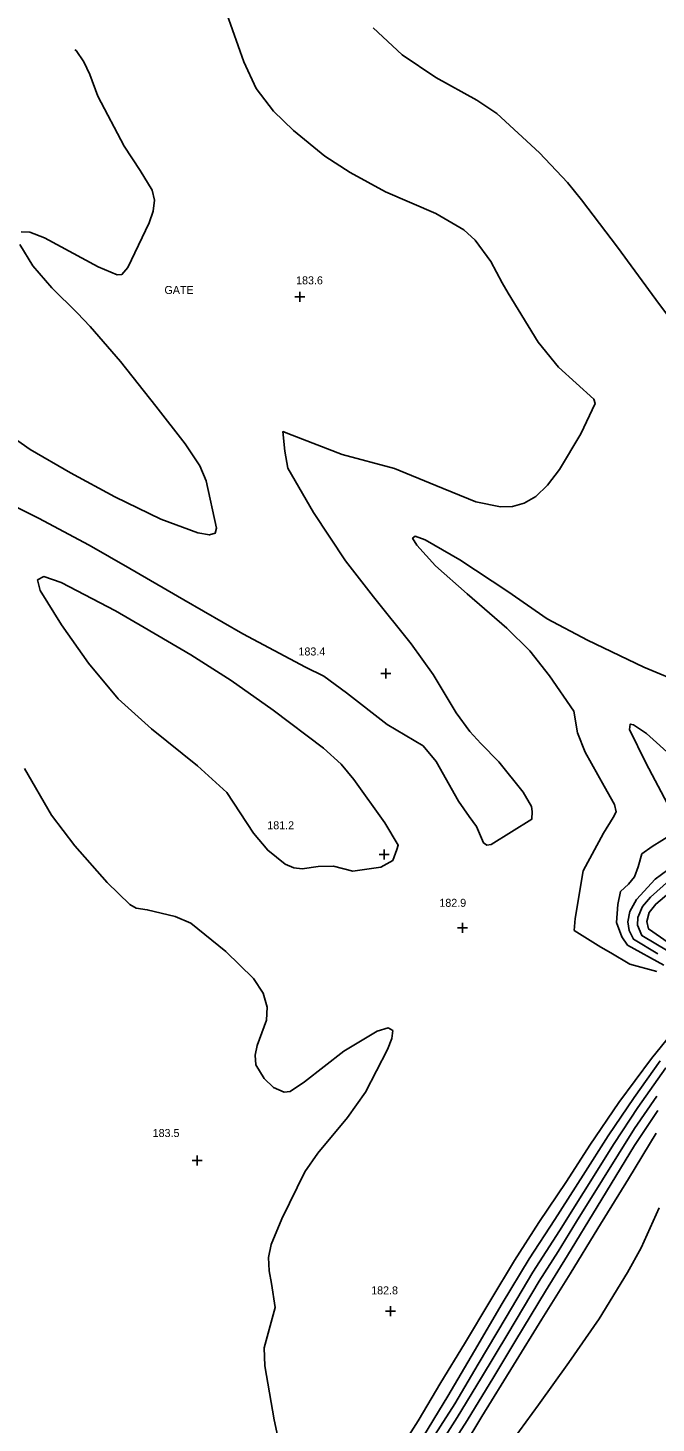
# Model space of a CAD drawing. Extents: x 1467615 to 2003689, y 770235 to 1108726.
# Drawn here: x 1995982 to 1996139.1, y 777168.5 to 777517.3 of the extents above; entities that cross this region are included whole.
import ezdxf

# ---------------------------------------------------------------- set-up
doc = ezdxf.new("R2010")
doc.units = 0
for name, color, linetype in [('RD_DTM_Major1', 7, 'Continuous'), ('RD_DTM_Minor1', 7, 'Continuous'), ('RD_DTM_Spot_Elev', 7, 'Continuous'), ('RD_TX_Misc1', 7, 'Continuous')]:
    doc.layers.add(name, color=color, linetype=linetype)

msp = doc.modelspace()

# ---------------------------------------------------------------- linework, layer by layer
at = {"layer": 'RD_DTM_Major1'}
for points in [[(1996139.5, 777285.81), (1996133.49, 777289.47), (1996132.41, 777291.64), (1996132.06, 777293.85), (1996132.58, 777296.37), (1996134.18, 777299.43), (1996138.87, 777304.46), (1996142.07, 777306.78)], [(1996081.64, 777162.14), (1996088.74, 777173.32), (1996094.57, 777183.29), (1996101.6, 777195.01), (1996108.27, 777206.23), (1996114.95, 777216.57), (1996120.98, 777226.19), (1996128.59, 777238.43), (1996134.57, 777247.38), (1996141.52, 777257.32)]]:
    msp.add_lwpolyline(points, dxfattribs=at)
at = {"layer": 'RD_DTM_Minor1'}
for points in [[(1995976.69, 777398.74), (1995984.68, 777394.69), (1995997.34, 777387.96), (1996007.53, 777382.13), (1996020.98, 777374.31), (1996035.75, 777365.81), (1996051.43, 777357.46), (1996055.98, 777355.19), (1996061.72, 777351.02), (1996071.87, 777343.17), (1996080.86, 777337.78), (1996084.08, 777333.87), (1996089.73, 777324.02), (1996092.37, 777320.15), (1996094.18, 777317.65), (1996095.92, 777313.6), (1996096.77, 777312.97), (1996097.86, 777313.16), (1996108.02, 777319.47), (1996108.1, 777321.39), (1996107.98, 777322.64), (1996105.86, 777326.27), (1996099.8, 777333.83), (1996095.26, 777338.37), (1996092.54, 777341.4), (1996089.07, 777346.03), (1996083.39, 777355.68), (1996077.87, 777363.33), (1996068.46, 777375.05), (1996061.45, 777384.07), (1996053.43, 777396.14), (1996047.03, 777407.18), (1996046.28, 777411.48), (1996045.8, 777416.34), (1996048.13, 777415.5), (1996060.62, 777410.62), (1996073.68, 777407.17), (1996084.04, 777402.84), (1996094.05, 777398.77), (1996100.21, 777397.55), (1996103.17, 777397.66), (1996106.08, 777398.47), (1996109, 777400.16), (1996111.95, 777402.94), (1996114.94, 777406.86), (1996120.31, 777415.82), (1996123.91, 777423.37), (1996123.51, 777424.45), (1996114.74, 777432.45), (1996109.58, 777438.72), (1996102.09, 777450.96), (1996100.61, 777453.5), (1996097.76, 777458.9), (1996093.82, 777464.21), (1996091.01, 777466.77), (1996084.01, 777470.86), (1996071.46, 777476.27), (1996062.59, 777481.13), (1996056.28, 777485.2), (1996048.39, 777491.63), (1996043.43, 777496.47), (1996039.13, 777502.15), (1996036.02, 777508.78), (1996031.79, 777520.75)], [(1996147.5, 777438.16), (1996139.05, 777449.39), (1996129.49, 777462.46), (1996120.48, 777474.29), (1996116.97, 777478.63), (1996109.92, 777486.01), (1996099.27, 777495.87), (1996094.26, 777499.23), (1996083.99, 777504.89), (1996075.64, 777510.49), (1996068.31, 777517.29)], [(1995980.32, 777466.3), (1995982.47, 777466.24), (1995986.14, 777464.8), (1995999.56, 777457.56), (1996004.34, 777455.55), (1996005.5, 777455.66), (1996007, 777457.39), (1996012.37, 777468.51), (1996013.34, 777471.41), (1996013.66, 777474.18), (1996013.11, 777476.7), (1996010.1, 777481.64), (1996006.1, 777487.7), (1995999.52, 777500.2), (1995997.49, 777505.65), (1995995.99, 777508.77), (1995994.04, 777511.6), (1995993.78, 777511.79)], [(1995969.53, 777420.99), (1995982.6, 777411.89), (1995992.66, 777406.06), (1996003.75, 777400.05), (1996015.29, 777394.48), (1996024.49, 777391.04), (1996027.39, 777390.53), (1996028.85, 777390.99), (1996029.2, 777392.21), (1996026.62, 777404.01), (1996024.98, 777407.79), (1996021.31, 777413.31), (1996013.99, 777422.73), (1996005.14, 777433.85), (1995997.6, 777442.58), (1995994.29, 777446.06), (1995988.02, 777452.25), (1995983.24, 777457.81), (1995980.01, 777463.15)], [(1996139.31, 777281.4), (1996132.56, 777283.25), (1996127.79, 777286.08), (1996125.29, 777287.46), (1996118.58, 777291.67), (1996118.85, 777294.69), (1996120.89, 777306.56), (1996125.98, 777316.01), (1996128.41, 777319.87), (1996129.09, 777321.28), (1996128.68, 777323.15), (1996126.09, 777327.74), (1996121.38, 777336.19), (1996119.49, 777341.06), (1996118.56, 777346.49), (1996112.45, 777355.28), (1996107.51, 777361.54), (1996101.75, 777367.18), (1996091.84, 777375.84), (1996083.95, 777382.83), (1996079.25, 777387.96), (1996078.22, 777389.7), (1996078.82, 777390.25), (1996081.37, 777389.26), (1996090.04, 777384.29), (1996101.99, 777376.38), (1996111.88, 777369.59), (1996121.98, 777364.19), (1996136, 777357.5), (1996146.46, 777353.11)], [(1996011.05, 777367.41), (1996022.72, 777360.54), (1996032.8, 777354.14), (1996043.35, 777346.74), (1996055.89, 777337.25), (1996060.38, 777333.24), (1996063.48, 777329.43), (1996071.27, 777318.6), (1996074.63, 777312.97), (1996074.27, 777311.91), (1996073.28, 777309.19), (1996070.28, 777307.47), (1996063.26, 777306.49), (1996058.46, 777307.75), (1996054.59, 777307.62), (1996050.62, 777307.03), (1996048.51, 777307.29), (1996046.31, 777308.24), (1996041.98, 777311.71), (1996038.46, 777316.01), (1996031.74, 777326.17), (1996024.44, 777332.82), (1996012.93, 777342.05), (1996004.6, 777349.59), (1995997.14, 777358.5), (1995990.44, 777368.04), (1995985.11, 777376.62), (1995984.41, 777379.29), (1995986.01, 777380.1), (1995990.34, 777378.66), (1996003.91, 777371.53), (1996011.05, 777367.41)], [(1996141.94, 777323.35), (1996136.55, 777333.59), (1996132.46, 777341.93), (1996132.65, 777343.25), (1996133.49, 777343.07), (1996136.72, 777340.87), (1996143.49, 777334.84)], [(1996045.19, 777161.99), (1996043.63, 777169.36), (1996041.28, 777182.8), (1996041.08, 777187.32), (1996043.88, 777197.43), (1996042.95, 777203.43), (1996042.35, 777206.61), (1996042.21, 777209.88), (1996042.85, 777213.19), (1996045.53, 777219.55), (1996051.22, 777231.37), (1996054.5, 777235.98), (1996061.96, 777244.88), (1996066.46, 777251.26), (1996071.91, 777261.9), (1996073.01, 777264.65), (1996073.26, 777266.65), (1996072.14, 777267.36), (1996069.36, 777266.46), (1996061.04, 777261.47), (1996051.2, 777253.82), (1996047.62, 777251.44), (1996046.11, 777251.26), (1996043.39, 777252.45), (1996041.13, 777254.65), (1996039.02, 777258.09), (1996038.8, 777260.53), (1996039.38, 777262.88), (1996041.64, 777269.23), (1996041.81, 777272.48), (1996040.85, 777276.01), (1996038.46, 777279.65), (1996031.5, 777286.4), (1996022.73, 777293.48), (1996018.86, 777295.16), (1996011.87, 777296.85), (1996009.06, 777297.24), (1996007.5, 777298.16), (1996001.79, 777303.68), (1995993.74, 777312.79), (1995987.94, 777320.44), (1995981.12, 777332.14)], [(1996141.01, 777282.95), (1996131.93, 777288), (1996130.55, 777290.09), (1996129.2, 777293.66), (1996129.5, 777298.19), (1996130.24, 777301.39), (1996132.19, 777303.22), (1996133.7, 777305.09), (1996134.63, 777307.55), (1996135.52, 777310.81), (1996138.1, 777312.62), (1996142.98, 777315.63)], [(1996142.13, 777286.45), (1996135.56, 777290.38), (1996134.49, 777292.95), (1996134.55, 777294.89), (1996135.67, 777297.69), (1996137.74, 777300.01), (1996142.44, 777304.23)], [(1996144.05, 777287.31), (1996137.22, 777292.05), (1996136.78, 777293.91), (1996137.39, 777296.15), (1996139, 777298.25), (1996143.38, 777301.92)], [(1996073.74, 777159.95), (1996079.57, 777169.13), (1996085.25, 777178.7), (1996091.16, 777188.32), (1996097.78, 777199.37), (1996103.71, 777209.14), (1996109.8, 777218.65), (1996116.68, 777228.9), (1996122.51, 777237.96), (1996129.77, 777248.69), (1996137.99, 777259.69), (1996144.37, 777267.6)], [(1996079.8, 777163.35), (1996087.01, 777175.28), (1996093.66, 777186.63), (1996100.64, 777198.4), (1996107.37, 777209.56), (1996113.81, 777219.44), (1996120.89, 777230.47), (1996127.1, 777240.31), (1996133.6, 777249.93), (1996140.14, 777259.06)], [(1996078.99, 777153.69), (1996089.39, 777169.89), (1996095.48, 777179.95), (1996102.03, 777190.84), (1996109.9, 777204.01), (1996114.6, 777211.43), (1996119.24, 777218.91), (1996125.69, 777229.36), (1996133.71, 777242.19), (1996139.27, 777250.21)], [(1996081.88, 777153.57), (1996091.84, 777169.15), (1996098.53, 777180.11), (1996104.05, 777189.27), (1996111.42, 777201.5), (1996116.91, 777210.45), (1996124.35, 777222.62), (1996133.72, 777237.94), (1996139.53, 777246.65)], [(1996086.72, 777155.49), (1996095.54, 777170.18), (1996103.41, 777183.02), (1996110.5, 777194.52), (1996117.6, 777205.87), (1996124.57, 777217.17), (1996132.19, 777229.6), (1996139.16, 777240.96)], [(1996103.34, 777164.41), (1996109.69, 777173.13), (1996117.26, 777183.67), (1996124.87, 777194.57), (1996131.93, 777206.18), (1996135.34, 777212.31), (1996139.91, 777222.33)]]:
    msp.add_lwpolyline(points, dxfattribs=at)
at = {"layer": 'RD_DTM_Spot_Elev'}
for p, q in [((1996050, 777448.75), (1996050, 777451.25)), ((1996048.75, 777450), (1996051.25, 777450)), ((1996071.54, 777354.65), (1996071.54, 777357.15)), ((1996070.29, 777355.9), (1996072.79, 777355.9)), ((1996071.08, 777309.39), (1996071.08, 777311.89)), ((1996069.83, 777310.64), (1996072.33, 777310.64)), ((1996089.44, 777292.36), (1996091.94, 777292.36)), ((1996090.69, 777291.11), (1996090.69, 777293.61)), ((1996024.37, 777232.88), (1996024.37, 777235.38)), ((1996023.12, 777234.13), (1996025.62, 777234.13)), ((1996072.72, 777195.23), (1996072.72, 777197.73)), ((1996071.47, 777196.48), (1996073.97, 777196.48))]:
    msp.add_line(p, q, dxfattribs=at)

# ---------------------------------------------------------------- texts
for s, p in [('183.6', (1996049.08, 777453.16)), ('183.4', (1996049.67, 777360.39)), ('181.2', (1996041.88, 777316.95)), ('182.9', (1996084.91, 777297.57)), ('183.5', (1996013.21, 777240.03)), ('182.8', (1996067.86, 777200.7))]:
    msp.add_text(s, height=2, dxfattribs=at).set_placement(p)
at = {"layer": 'RD_TX_Misc1'}
msp.add_text('GATE', height=2, dxfattribs=at).set_placement((1996016.16, 777450.75))

doc.saveas('drawing.dxf')
